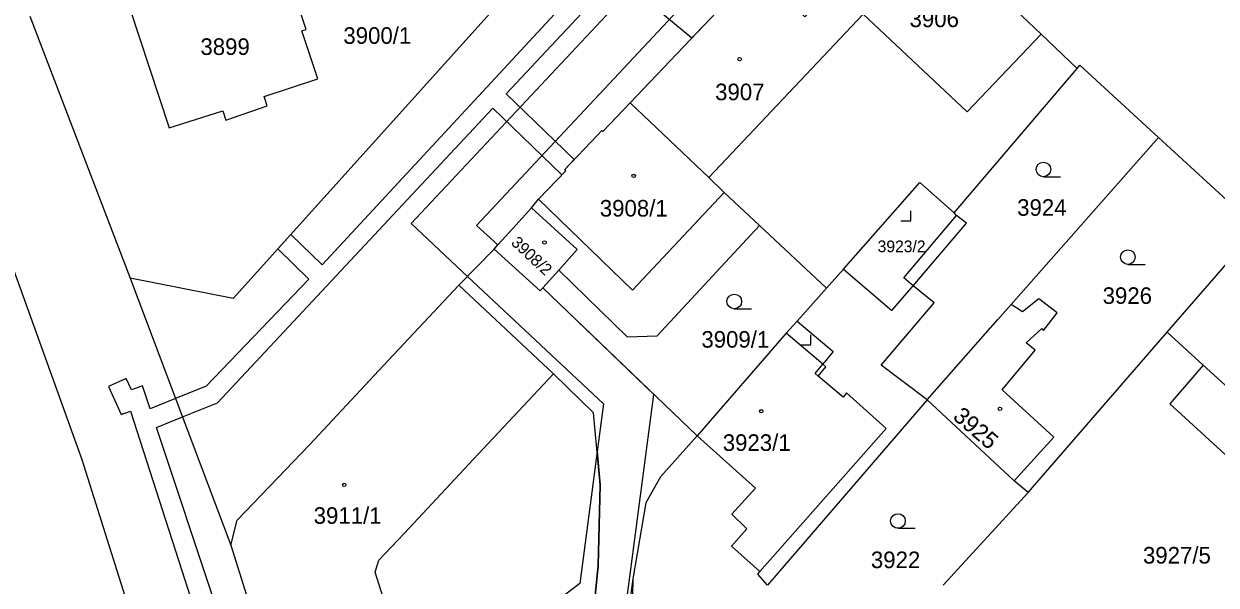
# Model space of a CAD drawing. Extents: x -756746 to -753363, y -1166406 to -1161727.
# Drawn here: x -756329.6 to -756207.5, y -1165520.8 to -1165463.3 of the extents above; entities that cross this region are included whole.
import ezdxf

# ---------------------------------------------------------------- set-up
doc = ezdxf.new("R2010")
doc.units = 0
for name, color, linetype in [('Hranice parcel', 7, 'Continuous'), ('Parcelní čísla', 7, 'Continuous'), ('Vnitřní kresba', 7, 'Continuous'), ('Věcná břemena k části', 7, 'Continuous'), ('Značky budov', 7, 'Continuous'), ('Značky kultur', 7, 'Continuous')]:
    doc.layers.add(name, color=color, linetype=linetype)

msp = doc.modelspace()

# ---------------------------------------------------------------- linework, layer by layer
at = {"layer": 'Hranice parcel'}
for p, q in [((-756267.54, -1165471.4), (-756254.65, -1165457.89)), ((-756328.99, -1165462.54), (-756318.74, -1165489.37)), ((-756225.44, -1165464.38), (-756221.77, -1165467.9)), ((-756234.35, -1165482.67), (-756221.77, -1165467.9)), ((-756228.51, -1165492.07), (-756213.43, -1165474.97)), ((-756213.43, -1165474.97), (-756203.3, -1165484.26)), ((-756279.55, -1165484.29), (-756277.64, -1165482.19)), ((-756254.29, -1165483.97), (-756247.43, -1165490.4)), ((-756212.53, -1165494.9), (-756203.3, -1165484.26)), ((-756285.08, -1165490.11), (-756281.47, -1165486.41)), ((-756276.75, -1165490.68), (-756281.47, -1165486.41)), ((-756318.74, -1165489.37), (-756308.42, -1165516.73)), ((-756274.84, -1165488.55), (-756276.47, -1165490.37)), ((-756275.38, -1165499.19), (-756285.08, -1165490.11)), ((-756276.47, -1165490.37), (-756276.75, -1165490.68)), ((-756276.47, -1165490.37), (-756260.67, -1165505.55)), ((-756251.55, -1165495.02), (-756260.67, -1165505.55)), ((-756226.78, -1165511.33), (-756212.53, -1165494.9)), ((-756228.22, -1165510.14), (-756237.11, -1165501.85)), ((-756226.78, -1165511.33), (-756228.22, -1165510.14)), ((-756235.47, -1165520.85), (-756226.78, -1165511.33))]:
    msp.add_line(p, q, dxfattribs=at)
for points in [[(-756292.62, -1165708.1), (-756291.19, -1165648.7), (-756290.89, -1165630.89), (-756290.24, -1165614.03), (-756291.21, -1165610.06), (-756302.74, -1165574.26), (-756310.88, -1165548.49), (-756323.64, -1165508), (-756337.93, -1165468.42), (-756358.43, -1165418.45), (-756368.85, -1165398.15), (-756409.24, -1165342.83), (-756436.19, -1165309.61), (-756456.31, -1165288.98), (-756449.84, -1165283.06)], [(-756245.07, -1165447.73), (-756244.17, -1165447.42), (-756243.12, -1165447.75), (-756239.44, -1165451.1), (-756239.07, -1165451.44), (-756225.44, -1165464.38)], [(-756313.27, -1165456.32), (-756319.84, -1165458.49), (-756314.73, -1165473.97), (-756309.24, -1165472.23), (-756308.93, -1165473.19), (-756304.71, -1165471.71), (-756305.02, -1165470.76), (-756299.52, -1165468.96), (-756301.14, -1165464.04), (-756300.71, -1165463.9), (-756301.96, -1165460.11), (-756302.39, -1165460.25), (-756304.05, -1165455.21), (-756309.72, -1165457.08), (-756310.25, -1165455.48), (-756313.22, -1165456.46), (-756313.27, -1165456.32)], [(-756254.65, -1165457.89), (-756249.64, -1165462.6), (-756246.95, -1165459.76), (-756243.66, -1165462.34), (-756233.01, -1165472.33), (-756225.44, -1165464.38)], [(-756280.63, -1165460.82), (-756308.17, -1165491.45), (-756318.74, -1165489.37)], [(-756221.77, -1165467.9), (-756221.49, -1165467.57), (-756213.43, -1165474.97)], [(-756277.64, -1165482.19), (-756276.91, -1165481.27), (-756274.13, -1165478.37), (-756274.24, -1165478.27), (-756270.88, -1165474.72), (-756270.44, -1165474.25), (-756270.33, -1165474.35), (-756267.54, -1165471.4)], [(-756267.54, -1165471.4), (-756259.47, -1165479.05), (-756257.9, -1165480.59), (-756254.29, -1165483.97)], [(-756247.43, -1165490.4), (-756245.7, -1165488.45), (-756237.88, -1165479.58), (-756234.35, -1165482.67)], [(-756277.64, -1165482.19), (-756272.95, -1165486.44), (-756274.84, -1165488.55)], [(-756237.11, -1165501.85), (-756241.83, -1165498.29), (-756236.39, -1165491.92), (-756238.54, -1165490.15), (-756239.5, -1165489.36), (-756234.1, -1165482.95), (-756234.35, -1165482.67)], [(-756281.47, -1165486.41), (-756281.07, -1165485.96), (-756279.55, -1165484.29)], [(-756274.84, -1165488.55), (-756267.85, -1165495.39), (-756264.77, -1165495.28), (-756254.29, -1165483.97)], [(-756308.42, -1165516.73), (-756307.79, -1165514.19), (-756300.38, -1165506.45), (-756292.79, -1165498.34), (-756285.08, -1165490.11)], [(-756247.43, -1165490.4), (-756250.43, -1165493.77), (-756251.55, -1165495.02)], [(-756237.11, -1165501.85), (-756233.15, -1165497.34), (-756229.87, -1165493.61), (-756228.51, -1165492.07)], [(-756228.22, -1165510.14), (-756224.16, -1165505.68), (-756229.42, -1165500.81), (-756226.06, -1165496.76), (-756226.98, -1165496), (-756225.37, -1165494.54), (-756225.19, -1165494.74), (-756223.79, -1165492.94), (-756225.68, -1165491.51), (-756227.35, -1165492.82), (-756228.51, -1165492.07)], [(-756254.24, -1165519.45), (-756241.33, -1165504.79), (-756245.39, -1165501.12), (-756245.71, -1165501.59), (-756248.29, -1165499.41), (-756247.49, -1165498.45), (-756247.81, -1165498.19), (-756251.55, -1165495.02)], [(-756212.53, -1165494.9), (-756208.84, -1165498.29), (-756212.26, -1165502.25), (-756204.63, -1165509.26), (-756201.09, -1165505.4), (-756200.1, -1165506.31), (-756203.64, -1165510.17), (-756194.03, -1165518.97)], [(-756286.76, -1165540.62), (-756291.44, -1165526.53), (-756293.64, -1165519.5), (-756293.26, -1165518.28), (-756290.69, -1165515.53), (-756283.1, -1165507.42), (-756275.38, -1165499.19)], [(-756285.47, -1165540.17), (-756281.6, -1165538.83), (-756276.31, -1165537.01), (-756274, -1165534.16), (-756271.87, -1165529.81), (-756271.4, -1165524.65), (-756270.82, -1165518.81), (-756270.6, -1165510.57), (-756271.27, -1165503.19), (-756275.38, -1165499.19)], [(-756237.11, -1165501.85), (-756253.48, -1165520.82), (-756254.47, -1165519.71), (-756254.24, -1165519.45)], [(-756260.67, -1165505.55), (-756264.42, -1165509.74), (-756265.94, -1165512.39), (-756267.27, -1165520.19), (-756268.28, -1165527.74)], [(-756254.24, -1165519.45), (-756257.15, -1165516.83), (-756255.59, -1165515.06), (-756257.11, -1165513.57), (-756254.7, -1165510.89), (-756260.67, -1165505.55)], [(-756308.42, -1165516.73), (-756305.22, -1165526.97), (-756299.64, -1165544.75)]]:
    msp.add_lwpolyline(points, dxfattribs=at)
at = {"layer": 'Vnitřní kresba'}
for p, q in [((-756259.47, -1165479.05), (-756243.66, -1165462.34)), ((-756267.28, -1165490.6), (-756257.9, -1165480.59)), ((-756276.91, -1165481.27), (-756267.28, -1165490.6)), ((-756233.09, -1165483.76), (-756234.1, -1165482.95)), ((-756238.54, -1165490.15), (-756233.09, -1165483.76)), ((-756245.7, -1165488.45), (-756240.72, -1165492.7)), ((-756240.72, -1165492.7), (-756238.54, -1165490.15)), ((-756250.43, -1165493.77), (-756246.74, -1165496.88)), ((-756246.74, -1165496.88), (-756247.81, -1165498.19)), ((-756248.59, -1165499.16), (-756247.81, -1165498.19)), ((-756248.29, -1165499.41), (-756248.59, -1165499.16)), ((-756208.84, -1165498.29), (-756201.09, -1165505.4)), ((-756267.27, -1165520.19), (-756267.35, -1165526.22))]:
    msp.add_line(p, q, dxfattribs=at)
at = {"layer": 'Věcná břemena k části'}
for points in [[(-756248.49, -1165439.47), (-756289.96, -1165483.78), (-756284.19, -1165489.2), (-756270.27, -1165502.25), (-756270.91, -1165507.14), (-756270.6, -1165510.57), (-756270.82, -1165518.81), (-756271.4, -1165524.65), (-756271.53, -1165526.06), (-756268.01, -1165523.37), (-756265.1, -1165501.3), (-756276.47, -1165490.37), (-756276.75, -1165490.68), (-756281.47, -1165486.41), (-756281.07, -1165485.96), (-756283.28, -1165483.99), (-756241.55, -1165439.37)], [(-756266.19, -1165452.49), (-756299.07, -1165488.02), (-756302.27, -1165484.89), (-756303.61, -1165486.38), (-756300.44, -1165489.48), (-756310.94, -1165500.44), (-756314.08, -1165501.72), (-756316.68, -1165502.77), (-756317.48, -1165500.4), (-756318.6, -1165500.82), (-756319.13, -1165499.66), (-756320.95, -1165500.48), (-756319.66, -1165503.36), (-756318.71, -1165503), (-756280.01, -1165623.11), (-756282.15, -1165720.55)], [(-756310.07, -1165522.64), (-756316.05, -1165504.67), (-756313.38, -1165503.59), (-756309.8, -1165502.14), (-756281.6, -1165471.95), (-756274.53, -1165478.79), (-756274.13, -1165478.37), (-756274.24, -1165478.27), (-756273.26, -1165477.23), (-756280.24, -1165470.49), (-756268.91, -1165458.37), (-756261.2, -1165464.76), (-756259.82, -1165463.31)]]:
    msp.add_lwpolyline(points, dxfattribs=at)
msp.add_lwpolyline([(-756270.91, -1165507.14), (-756272.69, -1165520.65), (-756283.3, -1165528.75), (-756284.64, -1165535.21), (-756288.17, -1165536.37), (-756286.76, -1165540.62), (-756285.47, -1165540.17), (-756281.6, -1165538.83), (-756280.18, -1165538.34), (-756278.78, -1165531.59), (-756271.53, -1165526.06), (-756271.4, -1165524.65), (-756270.82, -1165518.81), (-756270.6, -1165510.57)], close=True, dxfattribs=at)
at = {"layer": 'Značky budov'}
for centre in [(-756256.32, -1165466.94), (-756267.17, -1165478.9), (-756276.3, -1165485.73), (-756254.11, -1165503.02), (-756229.66, -1165502.77), (-756296.81, -1165510.56)]:
    msp.add_circle(centre, 0.175, dxfattribs=at)
at = {"layer": 'Značky kultur'}
for p, q in [((-756225.21, -1165478.99), (-756223.46, -1165478.99)), ((-756239.8, -1165483.49), (-756238.8, -1165483.49)), ((-756238.8, -1165483.49), (-756238.8, -1165482.49)), ((-756216.56, -1165487.97), (-756214.81, -1165487.97)), ((-756256.87, -1165492.52), (-756255.12, -1165492.52)), ((-756249.02, -1165496.2), (-756249.02, -1165495.2)), ((-756250.02, -1165496.2), (-756249.02, -1165496.2)), ((-756240.11, -1165515.01), (-756238.36, -1165515.01))]:
    msp.add_line(p, q, dxfattribs=at)
for centre in [(-756225.21, -1165478.24), (-756216.56, -1165487.22), (-756256.87, -1165491.77), (-756240.11, -1165514.26)]:
    msp.add_circle(centre, 0.75, dxfattribs=at)

# ---------------------------------------------------------------- texts
at = {"layer": 'Parcelní čísla'}
for s, height, p in [('3906', 1.7, (-756238.92, -1165463.66)), ('3900/1', 1.7, (-756296.9, -1165465.37)), ('3899', 1.7, (-756311.54, -1165466.51)), ('3907', 1.7, (-756258.83, -1165471.15)), ('3908/1', 1.7, (-756270.64, -1165483.07)), ('3924', 1.7, (-756227.9, -1165482.99)), ('3923/2', 1.2, (-756242.19, -1165486.72)), ('3926', 1.7, (-756219.15, -1165492.02)), ('3909/1', 1.7, (-756260.24, -1165496.5)), ('3923/1', 1.7, (-756258.05, -1165507.08)), ('3911/1', 1.7, (-756299.94, -1165514.55)), ('3922', 1.7, (-756242.88, -1165519.09)), ('3927/5', 1.7, (-756215.02, -1165518.62))]:
    msp.add_text(s, height=height, dxfattribs=at).set_placement(p)
for s, height, rotation, p in [('3908/2', 1.2, 317, (-756279.81, -1165485.85)), ('3925', 1.7, 319, (-756234.59, -1165503.72))]:
    msp.add_text(s, height=height, rotation=rotation, dxfattribs=at).set_placement(p)

doc.saveas('drawing.dxf')
